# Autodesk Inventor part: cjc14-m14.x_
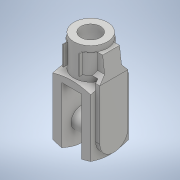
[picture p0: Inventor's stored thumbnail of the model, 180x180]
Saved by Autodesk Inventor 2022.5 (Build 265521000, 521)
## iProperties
Part Number: cjc14-m14.x_
Material: 一般
Document SubType Name: Modeling
Designer: ImaoCorp
Density: 1 g/cm^3
Appearance: 既定
Sending System: SOLIDWORKS 2017-2017317
MC: AMD64
MC_MODEL: Intel64 Family 6 Model 60 Stepping 3, GenuineIntel
OS: Windows_NT
FRU: Parasolid Version 29.0, build 201,  4-17-2017
FORMAT: text
GUISE: transmit
KEY: cjc14-m14
FILE: cjc14-m14.x_t
DATE: Thu Apr 04 16:45:52 2019
Author: ImaoCorp
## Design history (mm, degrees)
feature "Base1"
node "ソリッド1"
